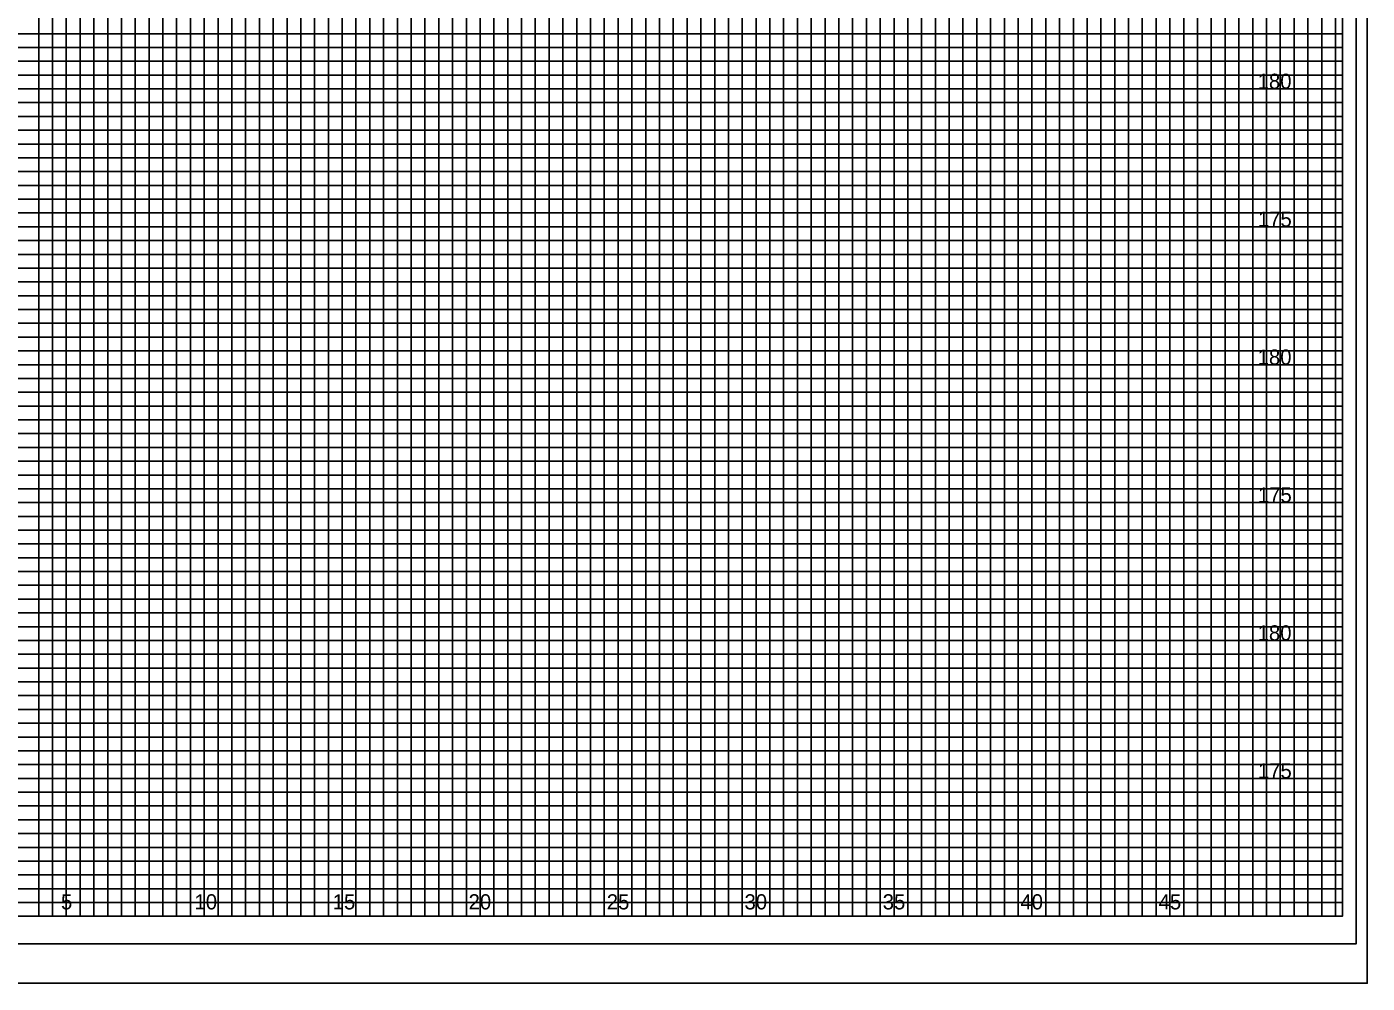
# Model space of a CAD drawing. Extents: x -4 to 103, y -2 to 209.
# Drawn here: x 54.82 to 103.4, y -2.43 to 32.25 of the extents above; entities that cross this region are included whole.
import ezdxf

# ---------------------------------------------------------------- set-up
doc = ezdxf.new("R2010")
doc.units = 0
for name, color, linetype in [('Old_Level_10', 7, 'Continuous'), ('Old_Level_16', 7, 'Continuous'), ('Old_Level_3', 7, 'Continuous'), ('Old_Level_4', 7, 'Continuous'), ('Old_Level_5', 7, 'Continuous'), ('Old_Level_6', 7, 'Continuous'), ('Old_Level_8', 7, 'Continuous'), ('Prop Dimension', 7, 'Continuous'), ('Prop XS Subgrade Earthwork', 7, 'Continuous')]:
    doc.layers.add(name, color=color, linetype=linetype)

msp = doc.modelspace()

# ---------------------------------------------------------------- linework, layer by layer
at = {"layer": 'Old_Level_10'}
for p, q in [((56.25, 0), (56.25, 65)), ((58.75, 0), (58.75, 65)), ((61.25, 0), (61.25, 65)), ((63.75, 0), (63.75, 65)), ((66.25, 0), (66.25, 65)), ((68.75, 0), (68.75, 65)), ((71.25, 0), (71.25, 65)), ((73.75, 0), (73.75, 65)), ((91.25, 0), (91.25, 63.425)), ((93.75, 0), (93.75, 63.425)), ((96.25, 0), (96.25, 63.425)), ((98.75, 0), (98.75, 63.425)), ((101.25, 0), (101.25, 63.425)), ((76.25, 0), (76.25, 62)), ((78.75, 0), (78.75, 62)), ((81.25, 0), (81.25, 62)), ((83.75, 0), (83.75, 62)), ((86.25, 0), (86.25, 62)), ((88.75, 0), (88.75, 62)), ((0, 30), (102.5, 30)), ((0, 27.5), (102.5, 27.5)), ((0, 25), (102.5, 25)), ((0, 22.5), (102.5, 22.5)), ((0, 20), (102.5, 20)), ((0, 17.5), (102.5, 17.5)), ((0, 15), (102.5, 15)), ((0, 12.5), (102.5, 12.5)), ((0, 10), (102.5, 10)), ((0, 7.5), (102.5, 7.5)), ((0, 5), (102.5, 5)), ((0, 2.5), (102.5, 2.5))]:
    msp.add_line(p, q, dxfattribs=at)
at = {"layer": 'Old_Level_3'}
msp.add_line((-3.5, -2.425), (103.4, -2.425), dxfattribs=at)
at = {"layer": 'Old_Level_4'}
msp.add_lwpolyline([(103, 66), (-2.8, 66), (-2.8, -1), (103, -1)], close=True, dxfattribs=at)
at = {"layer": 'Old_Level_5'}
msp.add_lwpolyline([(103.4, 67.4), (-3.5, 67.4), (-3.5, -2.425), (103.4, -2.425)], close=True, dxfattribs=at)
at = {"layer": 'Old_Level_6'}
msp.add_lwpolyline([(102.5, 65), (0, 65), (0, 0), (102.5, 0)], close=True, dxfattribs=at)
at = {"layer": 'Old_Level_8'}
for points in [[(56.25, 0), (56.25, 65)], [(58.75, 65), (58.75, 0), (61.25, 0), (61.25, 65)], [(63.75, 65), (63.75, 0), (66.25, 0), (66.25, 65)], [(68.75, 65), (68.75, 0), (71.25, 0), (71.25, 65)], [(73.75, 65), (73.75, 0), (76.25, 0), (76.25, 62)], [(88.75, 62), (88.75, 0), (91.25, 0), (91.25, 63.425)], [(93.75, 63.425), (93.75, 0), (96.25, 0), (96.25, 63.425)], [(98.75, 63.425), (98.75, 0), (101.25, 0), (101.25, 63.425)], [(78.75, 62), (78.75, 0), (81.25, 0), (81.25, 62)], [(83.75, 62), (83.75, 0), (86.25, 0), (86.25, 62)], [(0, 27.5), (102.5, 27.5), (102.5, 30), (0, 30)], [(0, 22.5), (102.5, 22.5), (102.5, 25), (0, 25)], [(0, 17.5), (102.5, 17.5), (102.5, 20), (0, 20)], [(0, 12.5), (102.5, 12.5), (102.5, 15), (0, 15)], [(0, 7.5), (102.5, 7.5), (102.5, 10), (0, 10)], [(0, 2.5), (102.5, 2.5), (102.5, 5), (0, 5)]]:
    msp.add_lwpolyline(points, dxfattribs=at)
at = {"layer": 'Prop Dimension'}
for points in [[(54.75, 0), (55.25, 0), (55.25, 65)], [(55.75, 65), (55.75, 0), (56.75, 0), (56.75, 65)], [(57.25, 65), (57.25, 0), (57.75, 0), (57.75, 65)], [(58.25, 65), (58.25, 0), (59.25, 0), (59.25, 65)], [(59.75, 65), (59.75, 0), (60.25, 0), (60.25, 65)], [(60.75, 65), (60.75, 0), (61.75, 0), (61.75, 65)], [(62.25, 65), (62.25, 0), (62.75, 0), (62.75, 65)], [(63.25, 65), (63.25, 0), (64.25, 0), (64.25, 65)], [(64.75, 65), (64.75, 0), (65.25, 0), (65.25, 65)], [(65.75, 65), (65.75, 0), (66.75, 0), (66.75, 65)], [(67.25, 65), (67.25, 0), (67.75, 0), (67.75, 65)], [(68.25, 65), (68.25, 0), (69.25, 0), (69.25, 65)], [(69.75, 65), (69.75, 0), (70.25, 0), (70.25, 65)], [(70.75, 65), (70.75, 0), (71.75, 0), (71.75, 65)], [(72.25, 65), (72.25, 0), (72.75, 0), (72.75, 65)], [(73.25, 65), (73.25, 0), (74.25, 0), (74.25, 62)], [(89.75, 62), (89.75, 0), (90.25, 0), (90.25, 63.425)], [(90.75, 63.425), (90.75, 0), (91.75, 0), (91.75, 63.425)], [(92.25, 63.425), (92.25, 0), (92.75, 0), (92.75, 63.425)], [(93.25, 63.425), (93.25, 0), (94.25, 0), (94.25, 63.425)], [(94.75, 63.425), (94.75, 0), (95.25, 0), (95.25, 63.425)], [(95.75, 63.425), (95.75, 0), (96.75, 0), (96.75, 63.425)], [(97.25, 63.425), (97.25, 0), (97.75, 0), (97.75, 63.425)], [(98.25, 63.425), (98.25, 0), (99.25, 0), (99.25, 63.425)], [(99.75, 63.425), (99.75, 0), (100.25, 0), (100.25, 63.425)], [(100.25, 63.425), (100.75, 63.425), (100.75, 0), (101.75, 0), (101.75, 63.425), (102.25, 63.425), (102.25, 0)], [(74.75, 62), (74.75, 0), (75.25, 0), (75.25, 62)], [(75.75, 62), (75.75, 0), (76.75, 0), (76.75, 62)], [(77.25, 62), (77.25, 0), (77.75, 0), (77.75, 62)], [(78.25, 62), (78.25, 0), (79.25, 0), (79.25, 62)], [(79.75, 62), (79.75, 0), (80.25, 0), (80.25, 62)], [(80.75, 62), (80.75, 0), (81.75, 0), (81.75, 62)], [(82.25, 62), (82.25, 0), (82.75, 0), (82.75, 62)], [(83.25, 62), (83.25, 0), (84.25, 0), (84.25, 62)], [(84.75, 62), (84.75, 0), (85.25, 0), (85.25, 62)], [(85.75, 62), (85.75, 0), (86.75, 0), (86.75, 62)], [(87.25, 62), (87.25, 0), (87.75, 0), (87.75, 62)], [(88.25, 62), (88.25, 0), (89.25, 0), (89.25, 62)], [(0, 31.5), (102.5, 31.5), (102.5, 32), (0, 32)], [(0, 30.5), (102.5, 30.5), (102.5, 31), (0, 31)], [(0, 29), (102.5, 29), (102.5, 29.5), (0, 29.5)], [(0, 28), (102.5, 28), (102.5, 28.5), (0, 28.5)], [(0, 26.5), (102.5, 26.5), (102.5, 27), (0, 27)], [(0, 25.5), (102.5, 25.5), (102.5, 26), (0, 26)], [(0, 24), (102.5, 24), (102.5, 24.5), (0, 24.5)], [(0, 23), (102.5, 23), (102.5, 23.5), (0, 23.5)], [(0, 21.5), (102.5, 21.5), (102.5, 22), (0, 22)], [(0, 20.5), (102.5, 20.5), (102.5, 21), (0, 21)], [(0, 19), (102.5, 19), (102.5, 19.5), (0, 19.5)], [(0, 18), (102.5, 18), (102.5, 18.5), (0, 18.5)], [(0, 16.5), (102.5, 16.5), (102.5, 17), (0, 17)], [(0, 15.5), (102.5, 15.5), (102.5, 16), (0, 16)], [(0, 14), (102.5, 14), (102.5, 14.5), (0, 14.5)], [(0, 13), (102.5, 13), (102.5, 13.5), (0, 13.5)], [(0, 11.5), (102.5, 11.5), (102.5, 12), (0, 12)], [(0, 10.5), (102.5, 10.5), (102.5, 11), (0, 11)], [(0, 9), (102.5, 9), (102.5, 9.5), (0, 9.5)], [(0, 8), (102.5, 8), (102.5, 8.5), (0, 8.5)], [(0, 6.5), (102.5, 6.5), (102.5, 7), (0, 7)], [(0, 5.5), (102.5, 5.5), (102.5, 6), (0, 6)], [(0, 4), (102.5, 4), (102.5, 4.5), (0, 4.5)], [(0, 3), (102.5, 3), (102.5, 3.5), (0, 3.5)], [(0, 1.5), (102.5, 1.5), (102.5, 2), (0, 2)], [(0, 0.5), (102.5, 0.5), (102.5, 1), (0, 1)]]:
    msp.add_lwpolyline(points, dxfattribs=at)

# ---------------------------------------------------------------- texts
at = {"layer": 'Old_Level_16'}
for s, p in [('5', (56.0574, 0.25)), ('10', (60.8971, 0.25)), ('15', (65.9057, 0.25)), ('20', (70.8312, 0.25)), ('25', (75.8399, 0.25)), ('30', (80.8312, 0.25)), ('35', (85.8399, 0.25)), ('40', (90.8313, 0.25)), ('45', (95.8399, 0.25))]:
    msp.add_text(s, height=0.55, dxfattribs=at).set_placement(p)
at = {"layer": 'Prop XS Subgrade Earthwork'}
for s, p in [('180', (99.4296, 30)), ('175', (99.4383, 25)), ('180', (99.4296, 20)), ('175', (99.4383, 15)), ('180', (99.4296, 10)), ('175', (99.4383, 5))]:
    msp.add_text(s, height=0.55, dxfattribs=at).set_placement(p)

doc.saveas('drawing.dxf')
